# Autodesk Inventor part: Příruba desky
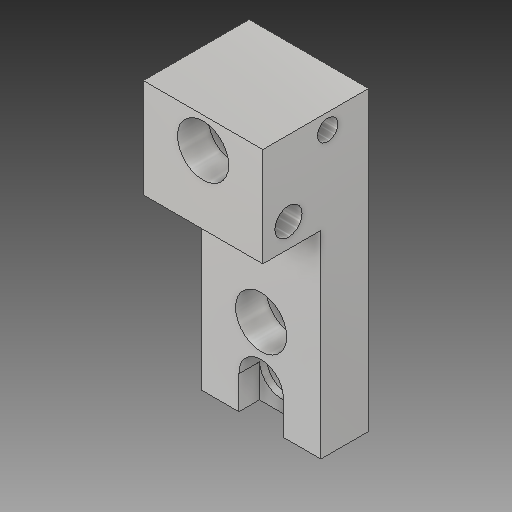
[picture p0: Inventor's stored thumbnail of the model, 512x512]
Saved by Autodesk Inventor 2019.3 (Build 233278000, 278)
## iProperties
Created: 2019-01
Part Number: Příruba desky
Material: Hliník 6061-AHC
Document SubType Name: Modeling
Designer: B-hon
Density: 2.7 g/cm^3
Appearance: Hliník – tmavý
Author: B-hon
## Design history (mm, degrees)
sketch "Náčrt1"
  geometry: L1 (-32.5, 40)-(32.5, 40); L2 (32.5, 40)-(32.5, -40); L3 (32.5, -40)-(-32.5, -40); L4 (-32.5, -40)-(-32.5, 40); L5 (-32.5, 40)-(32.5, -40); L6 (32.5, 40)-(-32.5, -40); 1 further point
  constraints: 12 end point, 2 midpoint, 2 parallel, 1 horizontal, 1 perpendicular
  dimensions: "d0" = 65 distance of L2.end L3.end; "d1" = 80 distance of L1.end L2.end
extrude "Vysunutí1" new body sketch "Náčrt1" distance "d2" = 26; taper "d3" = 0 deg
sketch "Náčrt2"
  geometry: L1 (-44.381, 28)-(47.748, 28); L2 (47.748, 28)-(47.748, 22); L3 (47.748, 22)-(-44.381, 22); L4 (-44.381, 22)-(-44.381, 28); L5 (-44.381, 28)-(47.748, 22); L6 (47.748, 28)-(-44.381, 22); L7 (-32.5, -40)-(32.5, -40) reference; L8 (-38.512, 18)-(43.239, 18); L9 (43.239, 18)-(43.239, -45.522); L10 (43.239, -45.522)-(-38.512, -45.522); L11 (-38.512, -45.522)-(-38.512, 18); L12 (-32.5, 40)-(-32.5, -40) reference; 2 further points
  constraints: 20 end point, 4 parallel, 2 horizontal, 2 midpoint, 2 perpendicular
  dimensions: "d4" = 6 distance of L1.end L2.end; "d5" = 65 distance from line of L7 point (1.683, 25); "d6" = 7 distance from line of L8 point (1.683, 25)
extrude "Vysunutí2" cut sketch "Náčrt2" distance "d10" = 14; taper "d11" = 0 deg
sketch "Náčrt3"
  geometry: L1 (-39.607, 44.84)-(-17.5, 44.84); L2 (-17.5, 44.84)-(-17.5, 11.926); L3 (-17.5, 11.926)-(-39.607, 11.926); L4 (-39.607, 11.926)-(-39.607, 44.84); L5 (17.5, 44.045)-(36.686, 44.045); L6 (36.686, 44.045)-(36.686, 9.931); L7 (36.686, 9.931)-(17.5, 9.931); L8 (17.5, 9.931)-(17.5, 44.045); L9 (-32.5, 40)-(-32.5, 18) reference; 1 further point
  constraints: 16 end point, 4 parallel, 2 horizontal, 2 perpendicular
  dimensions: "d12" = 35 distance between parallel lines of L8 L2; "d13" = 15 distance between parallel lines of L9 L2
extrude "Vysunutí3" cut sketch "Náčrt3" distance "d14" = 14; taper "d15" = 0 deg
sketch "Náčrt4"
  geometry: L1 (26, -58)-(14, -58) reference; L2 (0, 0)-(0, 22) reference; 2 further points
  dimensions: "d16" = 65 distance from line of L1 point (4.5, 7); "d17" = 4.5 distance from line of L2 point (4.5, 7)
hole "Díra1" sketch "Náčrt4" at (4.5, 7) diameter "d18" = 8; stored, may be unused: countersink angle "d22" = 90 deg, drill point angle "d24" = 118 deg; dims "d19" = 6, "d20" = 11, "d21" = 6.8, "d23" = 8
node "Upravit přímo1"
sketch "Náčrt6"
  geometry: L1 (32.5, -40)-(-32.5, -40) reference; C1 r 6.5 at (0, -30); 1 further point
  constraints: 1 centre point
  dimensions: "d39" = 13 diameter of C1; "d40" = 10 distance from line of L1 C1.centre
extrude "Vysunutí4" cut sketch "Náčrt6" distance "d41" = 8; taper "d42" = 0 deg
sketch "Náčrt7"
  geometry: L1 (-6.5, -61.308)-(6.5, -61.308); L2 (6.5, -61.308)-(6.5, -30.361); L3 (6.5, -30.361)-(-6.5, -30.361); L4 (-6.5, -30.361)-(-6.5, -61.308); L5 (-6.5, -61.308)-(6.5, -30.361); L6 (6.5, -61.308)-(-6.5, -30.361); 2 further points
  constraints: 12 end point, 2 midpoint, 2 parallel, 1 horizontal, 1 perpendicular
  dimensions: "d43" = 13 distance of L3.end L2.end
extrude "Vysunutí5" cut sketch "Náčrt7" distance "d44" = 6; taper "d45" = 0 deg
node "Upravit přímo2"
sketch "Náčrt9"
  geometry: L1 (17.5, 18)-(17.5, 45) reference; L2 (-6.5, -40)-(-32.5, -40) reference; 2 further points
  dimensions: "d58" = 17.5 distance from line of L1 point (0, -14); "d59" = 26 distance from line of L2 point (0, -14)
hole "Díra4" sketch "Náčrt9" at (0, -14) diameter "d60" = 8.4; stored, may be unused: countersink angle "d64" = 90 deg, drill point angle "d66" = 118 deg; dims "d61" = 16, "d62" = 15, "d63" = 9, "d65" = 8
sketch "Náčrt10"
  geometry: L1 (-48.128, 53.565)-(-17.5, 53.565); L2 (-17.5, 53.565)-(-17.5, -46.218); L3 (-17.5, -46.218)-(-48.128, -46.218); L4 (-48.128, -46.218)-(-48.128, 53.565); L5 (17.5, 54.3)-(38.723, 54.3); L6 (38.723, 54.3)-(38.723, -45.483); L7 (38.723, -45.483)-(17.5, -45.483); L8 (17.5, -45.483)-(17.5, 54.3); L9 (-17.5, 45)-(-17.5, 18) reference; L10 (17.5, 18)-(17.5, 45) reference; 1 further point
  constraints: 16 end point, 4 parallel, 2 horizontal, 2 perpendicular
  dimensions: "d67" = 0 distance between parallel lines of L9 L2; "d68" = 0 distance between parallel lines of L8 L10
extrude "Vysunutí6" cut sketch "Náčrt10" distance "d69" = 15; taper "d70" = 0 deg
node "Upravit přímo4"
sketch "Náčrt11"
  geometry: L1 (35, 29)-(0, 29) reference; L2 (35, 0)-(35, 29) reference; 2 further points
  dimensions: "d77" = 9 distance from line of L1 point (17.5, 20); "d78" = 17.5 distance from line of L2 point (17.5, 20)
hole "Díra5" sketch "Náčrt11" at (17.5, 20) diameter "d79" = 8.4; stored, may be unused: countersink angle "d83" = 90 deg, drill point angle "d85" = 118 deg; dims "d80" = 16, "d81" = 15, "d82" = 9, "d84" = 8
node "Upravit přímo5"
sketch "Náčrt12"
  geometry: L1 (14, 87)-(14, 0) reference; L2 (-17, 87)-(14, 87) reference; 2 further points
  dimensions: "d89" = 12 distance from line of L1 point (2, 82.5); "d90" = 4.5 distance from line of L2 point (2, 82.5)
hole "Díra6" sketch "Náčrt12" at (2, 82.5) diameter "d91" = 6; stored, may be unused: countersink angle "d95" = 90 deg, drill point angle "d97" = 118 deg; dims "d92" = 16, "d93" = 15, "d94" = 9, "d96" = 13
node "Těleso1"
feature "Posunout1" dims "d27" = 5
feature "Posunout2" dims "d48" = 3
feature "Posunout4" dims "d76" = 2
feature "Posunout5" dims "d88" = 2
other parameters: "d25" = 0, "d26" = 0, "d46" = 0, "d47" = 0, "d74" = 0, "d75" = 0, "d86" = 0, "d87" = 0
